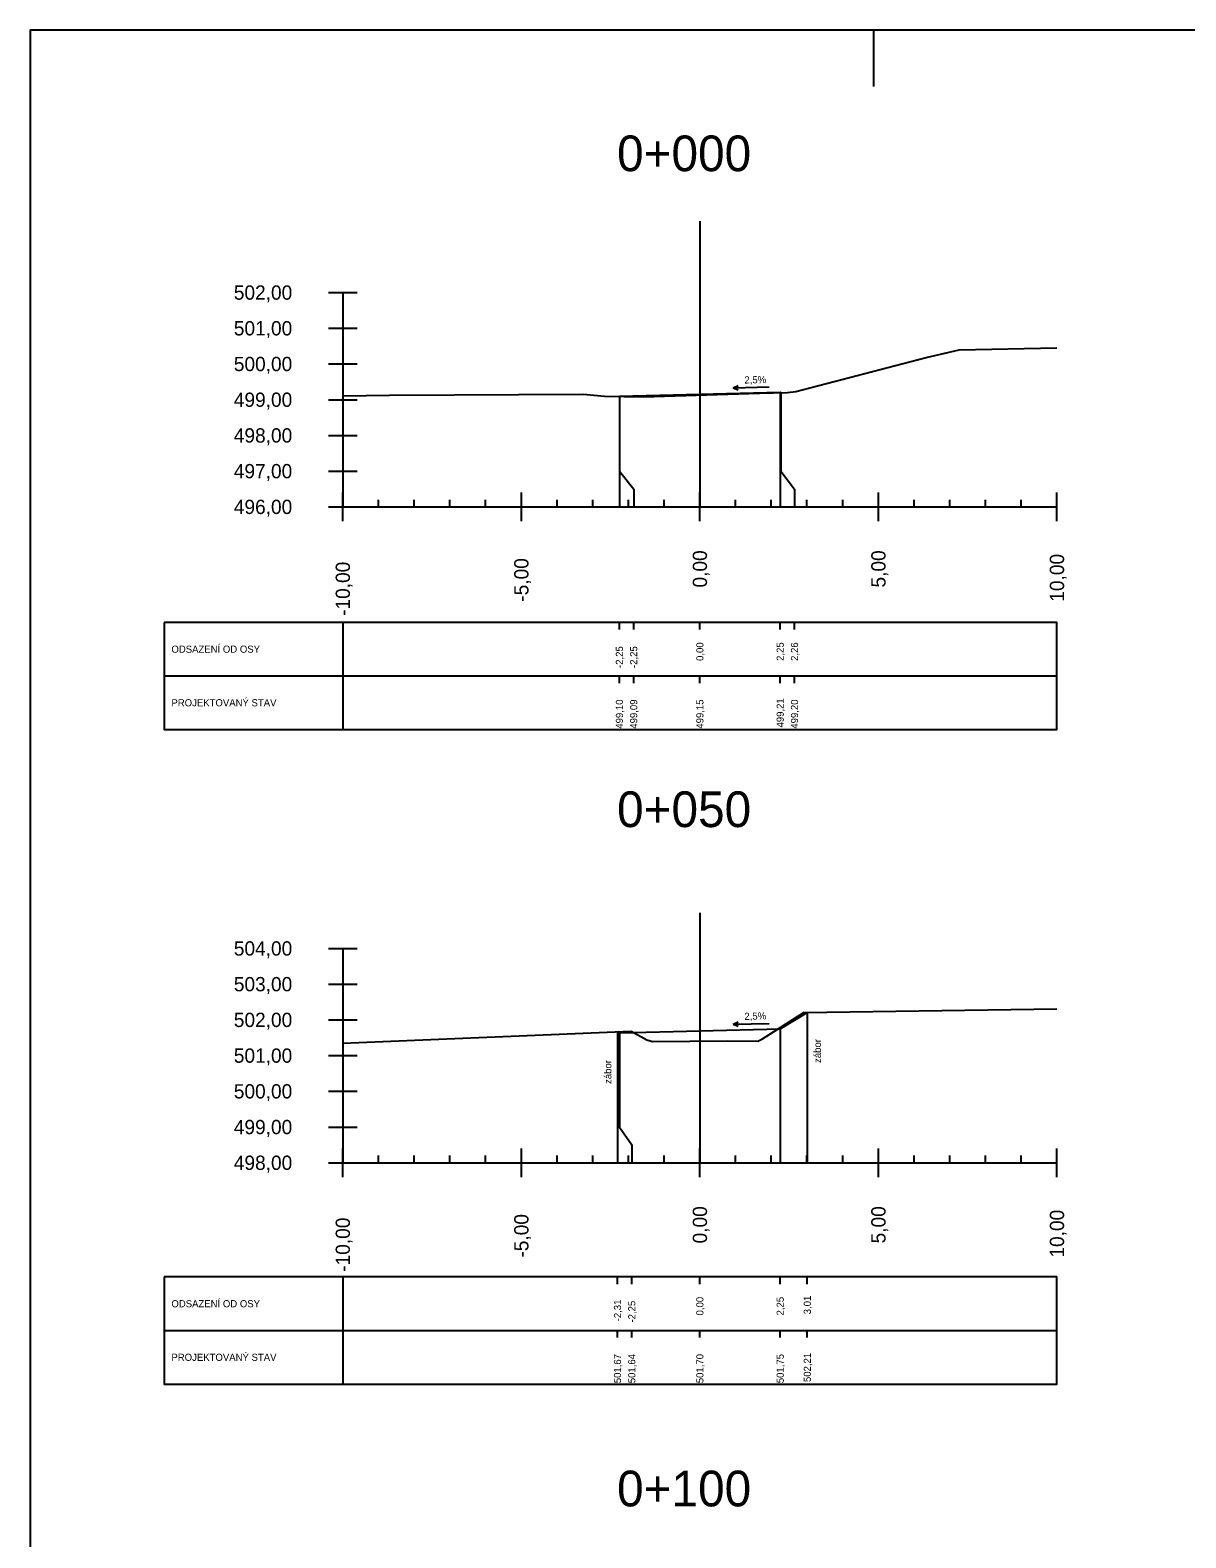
# Model space of a CAD drawing. Extents: x -631407 to -631215, y -1089700 to -1088598.
# Drawn here: x -631407.01 to -631374.65, y -1088807.44 to -1088765.23 of the extents above; entities that cross this region are included whole.
import ezdxf

# ---------------------------------------------------------------- set-up
doc = ezdxf.new("R2010")
doc.units = 0
for name, color, linetype in [('08_LEGENDA_HV', 7, 'Continuous'), ('59', 7, 'Continuous'), ('DTM-Breaklines', 7, 'Continuous'), ('NIVELETA_VYSKY', 7, 'Continuous'), ('REZ_BODY', 7, 'Continuous'), ('REZ_ODSTUPY', 7, 'Continuous'), ('REZ_POPIS', 7, 'Continuous'), ('REZ_RAMY', 7, 'Continuous'), ('REZ_STANICENI', 7, 'Continuous'), ('REZ_SVISLE', 7, 'Continuous'), ('REZ_TENKA', 7, 'Continuous'), ('REZ_TLUSTA', 7, 'Continuous'), ('TABULKA_POPIS', 7, 'Continuous'), ('TEREN', 7, 'Continuous'), ('zábor', 7, 'Continuous')]:
    doc.layers.add(name, color=color, linetype=linetype)

msp = doc.modelspace()

# ---------------------------------------------------------------- linework, layer by layer
at = {"layer": '08_LEGENDA_HV'}
msp.add_lwpolyline([(-631215.384, -1088943.435), (-631215.384, -1088765.235), (-631407.014, -1088765.235), (-631407.014, -1088943.435)], close=True, dxfattribs=at)
at = {"layer": '59'}
for p, q in [((-631398.658, -1088772.581), (-631397.858, -1088772.581)), ((-631398.258, -1088772.581), (-631398.258, -1088778.581)), ((-631398.658, -1088773.581), (-631397.858, -1088773.581)), ((-631398.658, -1088774.581), (-631397.858, -1088774.581)), ((-631398.658, -1088775.581), (-631397.858, -1088775.581)), ((-631398.658, -1088776.581), (-631397.858, -1088776.581)), ((-631398.658, -1088777.581), (-631397.858, -1088777.581)), ((-631398.658, -1088778.581), (-631397.858, -1088778.581)), ((-631398.658, -1088790.943), (-631397.858, -1088790.943)), ((-631398.258, -1088790.943), (-631398.258, -1088796.943)), ((-631398.658, -1088791.943), (-631397.858, -1088791.943)), ((-631398.658, -1088792.943), (-631397.858, -1088792.943)), ((-631398.658, -1088793.943), (-631397.858, -1088793.943)), ((-631398.658, -1088794.943), (-631397.858, -1088794.943)), ((-631398.658, -1088795.943), (-631397.858, -1088795.943)), ((-631398.658, -1088796.943), (-631397.858, -1088796.943))]:
    msp.add_line(p, q, dxfattribs=at)
at = {"layer": 'DTM-Breaklines'}
msp.add_line((-631383.384, -1088766.815), (-631383.384, -1088765.235), dxfattribs=at)
at = {"layer": 'REZ_RAMY'}
for p, q in [((-631403.258, -1088781.815), (-631403.258, -1088784.815)), ((-631398.258, -1088781.815), (-631398.258, -1088784.815)), ((-631390.512, -1088782.015), (-631390.512, -1088781.815)), ((-631390.112, -1088782.015), (-631390.112, -1088781.815)), ((-631388.258, -1088782.015), (-631388.258, -1088781.815)), ((-631386.008, -1088782.015), (-631386.008, -1088781.815)), ((-631385.608, -1088782.015), (-631385.608, -1088781.815)), ((-631403.258, -1088783.315), (-631378.258, -1088783.315)), ((-631390.512, -1088783.515), (-631390.512, -1088783.315)), ((-631390.112, -1088783.515), (-631390.112, -1088783.315)), ((-631388.258, -1088783.515), (-631388.258, -1088783.315)), ((-631386.008, -1088783.515), (-631386.008, -1088783.315)), ((-631385.608, -1088783.515), (-631385.608, -1088783.315)), ((-631403.258, -1088800.139), (-631403.258, -1088803.139)), ((-631398.258, -1088800.139), (-631398.258, -1088803.139)), ((-631390.566, -1088800.339), (-631390.566, -1088800.139)), ((-631390.166, -1088800.339), (-631390.166, -1088800.139)), ((-631388.258, -1088800.339), (-631388.258, -1088800.139)), ((-631386.008, -1088800.339), (-631386.008, -1088800.139)), ((-631385.249, -1088800.339), (-631385.249, -1088800.139)), ((-631403.258, -1088801.639), (-631378.258, -1088801.639)), ((-631390.566, -1088801.839), (-631390.566, -1088801.639)), ((-631390.166, -1088801.839), (-631390.166, -1088801.639)), ((-631388.258, -1088801.839), (-631388.258, -1088801.639)), ((-631386.008, -1088801.839), (-631386.008, -1088801.639)), ((-631385.249, -1088801.839), (-631385.249, -1088801.639))]:
    msp.add_line(p, q, dxfattribs=at)
for points in [[(-631403.258, -1088781.815), (-631403.258, -1088784.815), (-631378.258, -1088784.815), (-631378.258, -1088781.815)], [(-631403.258, -1088800.139), (-631403.258, -1088803.139), (-631378.258, -1088803.139), (-631378.258, -1088800.139)]]:
    msp.add_lwpolyline(points, close=True, dxfattribs=at)
at = {"layer": 'REZ_SVISLE'}
for points in [[(-631390.512, -1088775.484), (-631390.512, -1088777.581), (-631390.512, -1088778.081), (-631390.512, -1088778.581)], [(-631390.508, -1088775.486), (-631390.508, -1088777.581), (-631390.112, -1088778.081), (-631390.112, -1088778.581)], [(-631388.258, -1088775.43), (-631388.258, -1088777.581), (-631388.258, -1088778.081), (-631388.258, -1088778.581)], [(-631386.008, -1088775.374), (-631386.008, -1088777.581), (-631386.008, -1088778.081), (-631386.008, -1088778.581)], [(-631385.994, -1088775.382), (-631385.994, -1088777.581), (-631385.608, -1088778.081), (-631385.608, -1088778.581)], [(-631385.249, -1088792.734), (-631385.249, -1088795.943), (-631385.249, -1088796.443), (-631385.249, -1088796.943)], [(-631388.258, -1088793.245), (-631388.258, -1088795.943), (-631388.258, -1088796.443), (-631388.258, -1088796.943)], [(-631386.008, -1088793.189), (-631386.008, -1088795.943), (-631386.008, -1088796.443), (-631386.008, -1088796.943)], [(-631390.566, -1088793.272), (-631390.566, -1088795.943), (-631390.566, -1088796.443), (-631390.566, -1088796.943)], [(-631390.508, -1088793.301), (-631390.508, -1088795.943), (-631390.166, -1088796.443), (-631390.166, -1088796.943)]]:
    msp.add_lwpolyline(points, dxfattribs=at)
at = {"layer": 'REZ_TENKA'}
for p, q in [((-631397.258, -1088778.581), (-631397.258, -1088778.381)), ((-631396.258, -1088778.581), (-631396.258, -1088778.381)), ((-631395.258, -1088778.581), (-631395.258, -1088778.381)), ((-631394.258, -1088778.581), (-631394.258, -1088778.381)), ((-631392.258, -1088778.581), (-631392.258, -1088778.381)), ((-631391.258, -1088778.581), (-631391.258, -1088778.381)), ((-631390.258, -1088778.581), (-631390.258, -1088778.381)), ((-631389.258, -1088778.581), (-631389.258, -1088778.381)), ((-631387.258, -1088778.581), (-631387.258, -1088778.381)), ((-631386.258, -1088778.581), (-631386.258, -1088778.381)), ((-631385.258, -1088778.581), (-631385.258, -1088778.381)), ((-631384.258, -1088778.581), (-631384.258, -1088778.381)), ((-631382.258, -1088778.581), (-631382.258, -1088778.381)), ((-631381.258, -1088778.581), (-631381.258, -1088778.381)), ((-631380.258, -1088778.581), (-631380.258, -1088778.381)), ((-631379.258, -1088778.581), (-631379.258, -1088778.381)), ((-631397.258, -1088796.943), (-631397.258, -1088796.743)), ((-631396.258, -1088796.943), (-631396.258, -1088796.743)), ((-631395.258, -1088796.943), (-631395.258, -1088796.743)), ((-631394.258, -1088796.943), (-631394.258, -1088796.743)), ((-631392.258, -1088796.943), (-631392.258, -1088796.743)), ((-631391.258, -1088796.943), (-631391.258, -1088796.743)), ((-631390.258, -1088796.943), (-631390.258, -1088796.743)), ((-631389.258, -1088796.943), (-631389.258, -1088796.743)), ((-631387.258, -1088796.943), (-631387.258, -1088796.743)), ((-631386.258, -1088796.943), (-631386.258, -1088796.743)), ((-631385.258, -1088796.943), (-631385.258, -1088796.743)), ((-631384.258, -1088796.943), (-631384.258, -1088796.743)), ((-631382.258, -1088796.943), (-631382.258, -1088796.743)), ((-631381.258, -1088796.943), (-631381.258, -1088796.743)), ((-631380.258, -1088796.943), (-631380.258, -1088796.743)), ((-631379.258, -1088796.943), (-631379.258, -1088796.743))]:
    msp.add_line(p, q, dxfattribs=at)
at = {"layer": 'REZ_TLUSTA'}
for p, q in [((-631388.258, -1088770.581), (-631388.258, -1088778.581)), ((-631398.258, -1088778.981), (-631398.258, -1088778.181)), ((-631393.258, -1088778.981), (-631393.258, -1088778.181)), ((-631388.258, -1088778.981), (-631388.258, -1088778.181)), ((-631383.258, -1088778.981), (-631383.258, -1088778.181)), ((-631378.258, -1088778.981), (-631378.258, -1088778.181)), ((-631398.258, -1088778.581), (-631378.258, -1088778.581)), ((-631388.258, -1088789.943), (-631388.258, -1088796.943)), ((-631398.258, -1088797.343), (-631398.258, -1088796.543)), ((-631393.258, -1088797.343), (-631393.258, -1088796.543)), ((-631388.258, -1088797.343), (-631388.258, -1088796.543)), ((-631383.258, -1088797.343), (-631383.258, -1088796.543)), ((-631378.258, -1088797.343), (-631378.258, -1088796.543)), ((-631398.258, -1088796.943), (-631378.258, -1088796.943))]:
    msp.add_line(p, q, dxfattribs=at)
at = {"layer": 'TEREN'}
for points in [[(-631398.258, -1088775.468), (-631396.949, -1088775.452), (-631391.528, -1088775.424), (-631390.931, -1088775.477), (-631389.837, -1088775.496), (-631386.586, -1088775.401), (-631385.803, -1088775.376), (-631385.57, -1088775.352), (-631381.925, -1088774.395), (-631381, -1088774.183), (-631378.258, -1088774.131)], [(-631390.512, -1088775.484), (-631390.508, -1088775.486), (-631388.258, -1088775.43), (-631386.008, -1088775.374), (-631385.994, -1088775.382)], [(-631398.258, -1088793.598), (-631390.186, -1088793.256), (-631389.74, -1088793.499), (-631389.581, -1088793.547), (-631387.489, -1088793.528), (-631386.631, -1088793.54), (-631386.502, -1088793.477), (-631385.346, -1088792.735), (-631378.258, -1088792.636)], [(-631390.566, -1088793.272), (-631390.508, -1088793.301), (-631388.258, -1088793.245), (-631386.008, -1088793.189), (-631385.249, -1088792.734)]]:
    msp.add_lwpolyline(points, dxfattribs=at)
at = {"layer": 'zábor'}
for p, q in [((-631387.325, -1088775.25), (-631387.188, -1088775.186)), ((-631387.325, -1088775.25), (-631386.317, -1088775.225)), ((-631387.325, -1088775.25), (-631387.185, -1088775.308)), ((-631387.325, -1088793.066), (-631387.188, -1088793.001)), ((-631387.325, -1088793.066), (-631386.317, -1088793.04)), ((-631387.325, -1088793.066), (-631387.185, -1088793.123))]:
    msp.add_line(p, q, dxfattribs=at)

# ---------------------------------------------------------------- texts
at = {"layer": 'NIVELETA_VYSKY'}
for s, p in [('499,21', (-631385.908, -1088784.757)), ('499,10', (-631390.412, -1088784.791)), ('499,09', (-631390.012, -1088784.791)), ('499,15', (-631388.158, -1088784.791)), ('499,20', (-631385.508, -1088784.791)), ('501,67', (-631390.466, -1088803.115)), ('501,64', (-631390.066, -1088803.115)), ('501,70', (-631388.158, -1088803.115)), ('501,75', (-631385.908, -1088803.115)), ('502,21', (-631385.149, -1088803.082))]:
    msp.add_text(s, height=0.2, rotation=90, dxfattribs=at).set_placement(p)
at = {"layer": 'REZ_BODY'}
for s, p in [('-2,25', (-631390.412, -1088783.092)), ('-2,25', (-631390.012, -1088783.092)), ('0,00', (-631388.158, -1088782.894)), ('2,25', (-631385.908, -1088782.894)), ('2,26', (-631385.508, -1088782.894)), ('-2,31', (-631390.466, -1088801.383)), ('-2,25', (-631390.066, -1088801.416)), ('0,00', (-631388.158, -1088801.218)), ('2,25', (-631385.908, -1088801.218)), ('3,01', (-631385.149, -1088801.185))]:
    msp.add_text(s, height=0.2, rotation=90, dxfattribs=at).set_placement(p)
at = {"layer": 'REZ_ODSTUPY'}
for s, p in [('-10,00', (-631398.058, -1088781.633)), ('-5,00', (-631393.058, -1088781.236)), ('0,00', (-631388.058, -1088780.839)), ('5,00', (-631383.058, -1088780.839)), ('10,00', (-631378.058, -1088781.236)), ('0,00', (-631388.058, -1088799.201)), ('5,00', (-631383.058, -1088799.201)), ('10,00', (-631378.058, -1088799.598)), ('-10,00', (-631398.058, -1088799.995)), ('-5,00', (-631393.058, -1088799.598))]:
    msp.add_text(s, height=0.4, rotation=90, dxfattribs=at).set_placement(p)
at = {"layer": 'REZ_POPIS'}
for s, p in [('502,00', (-631401.31, -1088772.781)), ('501,00', (-631401.31, -1088773.781)), ('500,00', (-631401.31, -1088774.781)), ('499,00', (-631401.31, -1088775.781)), ('498,00', (-631401.31, -1088776.781)), ('497,00', (-631401.31, -1088777.781)), ('496,00', (-631401.31, -1088778.781)), ('504,00', (-631401.31, -1088791.143)), ('503,00', (-631401.31, -1088792.143)), ('502,00', (-631401.31, -1088793.143)), ('501,00', (-631401.31, -1088794.143)), ('500,00', (-631401.31, -1088795.143)), ('499,00', (-631401.31, -1088796.143)), ('498,00', (-631401.31, -1088797.143))]:
    msp.add_text(s, height=0.4, dxfattribs=at).set_placement(p)
at = {"layer": 'REZ_STANICENI'}
for s, p in [('0+000', (-631390.577, -1088769.184)), ('0+050', (-631390.577, -1088787.546)), ('0+100', (-631390.577, -1088806.563))]:
    msp.add_text(s, height=1, dxfattribs=at).set_placement(p)
at = {"layer": 'TABULKA_POPIS'}
for s, p in [('ODSAZENÍ OD OSY', (-631403.058, -1088782.665)), ('PROJEKTOVANÝ STAV', (-631403.058, -1088784.165)), ('ODSAZENÍ OD OSY', (-631403.058, -1088800.989)), ('PROJEKTOVANÝ STAV', (-631403.058, -1088802.489))]:
    msp.add_text(s, height=0.2, dxfattribs=at).set_placement(p)
at = {"layer": 'zábor'}
for s, rotation, p in [('2,5%', 1.4321, (-631387.009, -1088775.129)), ('2,5%', 1.4321, (-631387.009, -1088792.945)), ('zábor', 90, (-631384.866, -1088794.148)), ('zábor', 90, (-631390.736, -1088794.736))]:
    msp.add_text(s, height=0.2, rotation=rotation, dxfattribs=at).set_placement(p)

doc.saveas('drawing.dxf')
